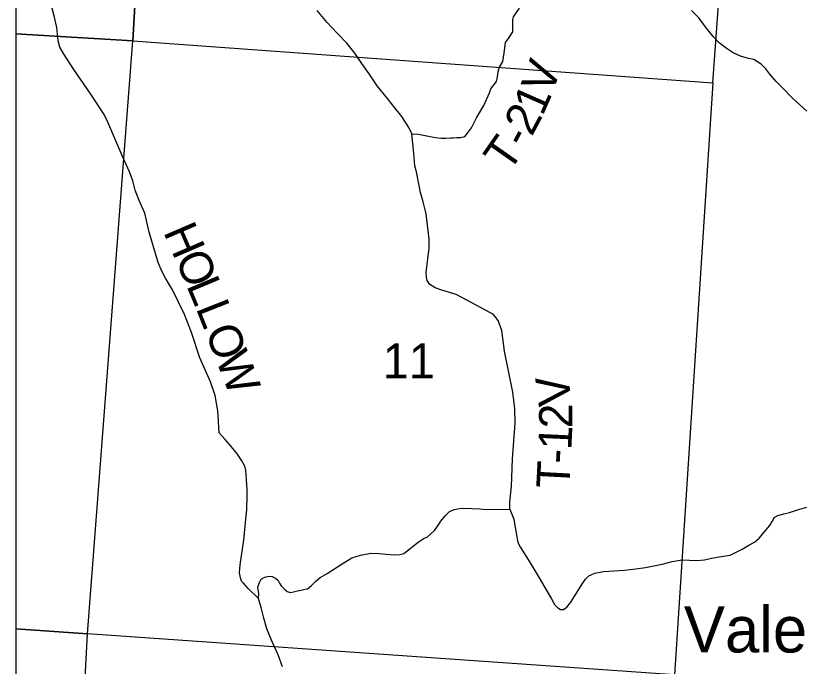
# Model space of a CAD drawing. Extents: x 0 to 34, y 0 to 22.
# Drawn here: x 2.1 to 3.447, y 18.997 to 20.111 of the extents above; entities that cross this region are included whole.
import ezdxf

# ---------------------------------------------------------------- set-up
doc = ezdxf.new("R2010")
doc.units = 0
for name, color, linetype in [('GM_X_Corporation', 7, 'Continuous'), ('GM_X_County_Road', 7, 'Continuous'), ('GM_X_Section_Text', 7, 'Continuous'), ('GM_X_Township_Road', 7, 'Continuous'), ('GM_X_Township_Road_Text', 7, 'Continuous'), ('GM_X_Unincorporated_Text', 7, 'Continuous'), ('SH_Data', 7, 'Continuous')]:
    doc.layers.add(name, color=color, linetype=linetype)

msp = doc.modelspace()

# ---------------------------------------------------------------- linework, layer by layer
at = {"layer": 'GM_X_Corporation'}
for points in [[(2.3483, 20.9), (2.1, 20.9), (2.1, 20.0805), (2.3005, 20.0682)], [(3.3608, 20.9), (2.3483, 20.9), (2.3005, 20.0682), (3.2948, 19.9968)], [(2.1, 20.0805), (2.1, 19.0613), (2.2229, 19.053), (2.3005, 20.0682)], [(2.3005, 20.0682), (3.2948, 19.9968), (3.2295, 18.9829), (2.2229, 19.053)], [(2.1, 19.0613), (2.1, 18.0382), (2.1667, 18.0342), (2.1822, 18.2802), (2.2023, 18.6627), (2.2229, 19.053)]]:
    msp.add_lwpolyline(points, close=True, dxfattribs=at)
msp.add_lwpolyline([(4.1215, 17.0136), (4.1603, 17.6679), (4.1853, 18.0392), (4.1964, 18.2095), (4.2079, 18.3668), (4.2088, 18.3789), (4.2282, 18.6426), (4.2537, 18.9868), (4.2536, 19.0552), (4.2737, 19.3421), (4.2893, 19.6309), (4.3029, 19.8336), (4.3134, 19.9898), (4.3401, 20.3869), (4.364, 20.7926), (4.3772, 20.9), (2.1, 20.9), (2.1, 14.9497)], dxfattribs=at)
at = {"layer": 'GM_X_County_Road'}
msp.add_lwpolyline([(3.4561, 19.948), (3.4313, 19.9702), (3.4138, 19.9887), (3.4035, 19.9989), (3.3928, 20.0116), (3.3856, 20.0207), (3.3775, 20.0284), (3.3652, 20.0364), (3.356, 20.0381), (3.3425, 20.042), (3.3298, 20.048), (3.3175, 20.056), (3.3056, 20.0651), (3.2954, 20.0759), (3.2856, 20.0878), (3.2791, 20.0973), (3.2709, 20.1077), (3.2583, 20.1203)], dxfattribs=at)
at = {"layer": 'GM_X_Township_Road'}
for points in [[(2.5573, 18.9965), (2.55, 19.0171), (2.5385, 19.0422), (2.5307, 19.0617), (2.5251, 19.0797), (2.5209, 19.0978), (2.5163, 19.1135), (2.4983, 19.1303), (2.4902, 19.1395), (2.4872, 19.1433), (2.4852, 19.149), (2.4838, 19.1573), (2.4846, 19.171), (2.491, 19.2133), (2.4949, 19.2548), (2.496, 19.2651), (2.497, 19.2899), (2.4969, 19.2993), (2.4957, 19.3168), (2.4943, 19.3325), (2.4926, 19.3403), (2.4878, 19.3494), (2.4802, 19.3606), (2.4671, 19.3768), (2.4588, 19.3857), (2.449, 19.3972), (2.448, 19.4058), (2.4477, 19.4173), (2.4463, 19.435), (2.4419, 19.4609), (2.4336, 19.4842), (2.4156, 19.5258), (2.4014, 19.5687), (2.3892, 19.5996), (2.369, 19.642), (2.3565, 19.6622), (2.3506, 19.6738), (2.3442, 19.6889), (2.3289, 19.7406), (2.3215, 19.7734), (2.3116, 19.7948), (2.3049, 19.8129), (2.301, 19.8285), (2.2953, 19.8443), (2.2835, 19.8695), (2.2581, 19.9294), (2.2514, 19.9426), (2.229, 19.9769), (2.1999, 20.0196), (2.182, 20.047), (2.1754, 20.0575), (2.173, 20.0685), (2.1706, 20.0912), (2.1657, 20.1113), (2.1574, 20.1434)], [(2.8045, 19.661), (2.804, 19.6639), (2.8037, 19.6715), (2.8086, 19.7141), (2.8086, 19.729), (2.8035, 19.7721), (2.7986, 19.7927), (2.794, 19.809), (2.7872, 19.8443), (2.7844, 19.8545), (2.7822, 19.8759), (2.7788, 19.909), (2.7738, 19.9203), (2.7618, 19.9389), (2.7496, 19.9539), (2.7371, 19.9696), (2.7196, 19.9912), (2.7056, 20.0117), (2.6931, 20.0295), (2.6813, 20.0471), (2.6673, 20.0644), (2.6508, 20.0815), (2.6339, 20.0997), (2.6166, 20.1206)], [(2.7788, 19.909), (2.7903, 19.9087), (2.8076, 19.9054), (2.8193, 19.9031), (2.829, 19.9017), (2.8371, 19.9017), (2.8453, 19.9024), (2.8499, 19.9026), (2.8558, 19.9029), (2.8625, 19.9028), (2.8696, 19.9045), (2.8746, 19.9103), (2.8811, 19.9195), (2.89, 19.9366), (2.9023, 19.9575), (2.9121, 19.9792), (2.9145, 19.9863), (2.9239, 19.9988), (2.926, 20.0067), (2.9269, 20.0154), (2.9295, 20.0234), (2.9349, 20.0333), (2.9374, 20.0478), (2.9397, 20.0654), (2.9458, 20.0743), (2.9519, 20.0841), (2.9523, 20.0922), (2.9519, 20.1006), (2.9522, 20.1052), (2.9532, 20.1096), (2.9634, 20.1243)], [(2.9467, 19.2661), (2.9472, 19.2792), (2.9497, 19.305), (2.9517, 19.3524), (2.9563, 19.4139), (2.9556, 19.4383), (2.9522, 19.4667), (2.938, 19.5368), (2.9331, 19.5725), (2.927, 19.5894), (2.9188, 19.5995), (2.8744, 19.6235), (2.8548, 19.6341), (2.8306, 19.6416), (2.819, 19.6457), (2.8099, 19.6514), (2.805, 19.6582), (2.8045, 19.661)], [(2.5163, 19.1135), (2.517, 19.1219), (2.5158, 19.128), (2.515, 19.1336), (2.5177, 19.141), (2.5208, 19.1464), (2.5271, 19.1499), (2.5339, 19.1514), (2.5397, 19.1509), (2.5455, 19.1482), (2.5499, 19.144), (2.5523, 19.1397), (2.5549, 19.1353), (2.5577, 19.1322), (2.5612, 19.1288), (2.5653, 19.1256), (2.571, 19.1237), (2.5761, 19.1246), (2.5805, 19.1257), (2.586, 19.1271), (2.5916, 19.1282), (2.5961, 19.1292), (2.6002, 19.1299), (2.6068, 19.1359), (2.6146, 19.143), (2.6221, 19.1491), (2.6337, 19.156), (2.6595, 19.1725), (2.676, 19.1833), (2.6911, 19.1875), (2.7087, 19.1908), (2.7232, 19.1902), (2.7351, 19.1894), (2.7492, 19.188), (2.7582, 19.1887), (2.7653, 19.1905), (2.7899, 19.2097), (2.7999, 19.2166), (2.8053, 19.2187), (2.8111, 19.2234), (2.8178, 19.2298), (2.8236, 19.2379), (2.8289, 19.246), (2.8364, 19.2549), (2.8436, 19.2623), (2.8517, 19.266), (2.8639, 19.268), (2.8822, 19.2674), (2.8957, 19.2672), (2.907, 19.266), (2.9467, 19.2661), (2.954, 19.2495), (2.9563, 19.2347), (2.9584, 19.2225), (2.9601, 19.2124), (2.9617, 19.207), (2.9652, 19.2008), (2.9821, 19.1743), (2.9989, 19.146), (3.0132, 19.1215), (3.0183, 19.1126), (3.0234, 19.1032), (3.0292, 19.0975), (3.0336, 19.0947), (3.0388, 19.0944), (3.0449, 19.0988), (3.0514, 19.1069), (3.0611, 19.1226), (3.0701, 19.1371), (3.0767, 19.1467), (3.0824, 19.1524), (3.0926, 19.157), (3.1074, 19.1598), (3.1435, 19.1621), (3.1627, 19.1641), (3.1793, 19.1662), (3.2081, 19.1722), (3.2255, 19.1768), (3.2421, 19.1796), (3.2673, 19.1786), (3.2805, 19.1796), (3.2925, 19.1825), (3.3094, 19.1851), (3.3245, 19.1876), (3.3339, 19.1919), (3.3451, 19.1976), (3.3569, 19.205), (3.3666, 19.2101), (3.3745, 19.2169), (3.3864, 19.2307), (3.3923, 19.2379), (3.3971, 19.2458), (3.4002, 19.2519), (3.4061, 19.2557), (3.4165, 19.2582), (3.4265, 19.2606), (3.4402, 19.2652), (3.456, 19.2697)]]:
    msp.add_lwpolyline(points, dxfattribs=at)
at = {"layer": 'SH_Data'}
msp.add_line((2.1, 20.9), (2.1, 14.1), dxfattribs=at)

# ---------------------------------------------------------------- texts
at = {"layer": 'GM_X_Section_Text'}
msp.add_text('11', height=0.06, rotation=0, dxfattribs=at).set_placement((2.7291, 19.4902))
at = {"layer": 'GM_X_Township_Road_Text'}
for s, rotation, p in [('V', 70.361, (3.0187, 19.9745)), ('1', 66.1704, (3.0029, 19.9383)), ('2', 61.971, (2.9845, 19.9033)), ('T', 55.0761, (2.9453, 19.8413)), ('-', 62.2182, (2.9736, 19.8828)), ('H', 293.3263, (2.3525, 19.7415)), ('O', 293.31, (2.3723, 19.6956)), ('L', 292.7118, (2.392, 19.6498)), ('L', 291.5754, (2.4083, 19.6109)), ('O', 290.834, (2.4239, 19.5715)), ('W', 291.34, (2.4419, 19.5243)), ('V', 97.6798, (3.0533, 19.448)), ('2', 90.281, (3.054, 19.405)), ('1', 87.3168, (3.0523, 19.3668)), ('-', 86.9872, (3.0511, 19.3432)), ('T', 86.9214, (3.0488, 19.3007))]:
    msp.add_text(s, height=0.0568, rotation=rotation, dxfattribs=at).set_placement(p)
at = {"layer": 'GM_X_Unincorporated_Text'}
msp.add_text('Vales Mills', height=0.078977, rotation=0, dxfattribs=at).set_placement((3.2453, 19.0209))

doc.saveas('drawing.dxf')
